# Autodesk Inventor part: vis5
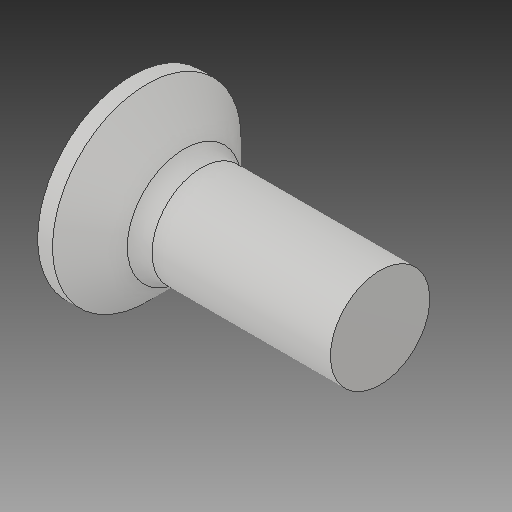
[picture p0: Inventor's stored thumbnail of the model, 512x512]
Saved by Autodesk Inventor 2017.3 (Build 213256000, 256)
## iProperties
Created: 1999-08
Part Number: vis5
Material: Générique
Document SubType Name: Modeling
Designer: ficho
Density: 1 g/cm^3
Appearance: Par défaut
Author: ficho
Sending System: SolidWorks 2009
Last Author: tof
Last Saved: 2010-07-07
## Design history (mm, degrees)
feature "RecessCore"
node "Solide1"
